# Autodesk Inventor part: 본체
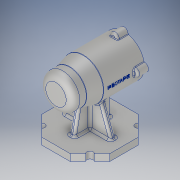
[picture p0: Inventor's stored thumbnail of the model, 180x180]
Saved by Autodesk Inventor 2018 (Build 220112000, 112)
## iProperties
Created: 2021-01
Part Number: 본체
Material: 알루미늄 6061
Document SubType Name: Modeling
Designer: home
Density: 2.7 g/cm^3
Appearance: 알루미늄 - 평지
Mass: 629.962 g
Surface Area: 613.777 cm^2
Volume: 233.319 cm^3
Author: home
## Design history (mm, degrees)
sketch "스케치1"
  geometry: L1 (0, 0)-(30, 0); L2 (30, 0)-(30, 60); L3 (30, 60)-(0, 60); L4 (0, 60)-(0, 0); L5 (30, 60)-(25, 80); L6 (25, 80)-(0, 80); L7 (0, 80)-(0, 60); L8 (0, 80)-(25, 80); L9 (25, 80)-(25, 100); L10 (25, 100)-(0, 100); L11 (0, 100)-(0, 80)
  constraints: 22 end point, 4 parallel, 3 horizontal, 3 perpendicular
  dimensions: "d5" = 30 distance of L1.start L1.end; "d6" = 60 distance of L1.end L2.end; "d9" = 20 distance of L8.end L9.end; "d10" = 25 distance of L9.end L10.end; "d11" = 100 distance between parallel lines of L1 L10
revolve "회전1" sketch "스케치1" stored, may be unused: angle "d12" = 90 deg
node "작업 평면1"
sketch "스케치2"
  geometry: L1 (0, 0)-(-21, 0); L2 (-21, 0)-(-21, 15); L3 (-21, 15)-(0, 15); L4 (0, 15)-(0, 0); L5 (0, 15)-(-24, 15); L6 (-24, 15)-(-24, 57); L7 (-24, 57)-(0, 57); L8 (0, 57)-(0, 15); L9 (0, 57)-(-21, 57); L10 (-21, 57)-(-21, 69); L11 (-21, 69)-(0, 69); L12 (0, 69)-(0, 57); L13 (0, 69)-(-17.5, 69); L14 (-17.5, 69)-(-17.5, 87); L15 (-17.5, 87)-(0, 87); L16 (0, 87)-(0, 69); L17 (0, 87)-(-16, 87); L18 (-16, 87)-(-16, 91); L19 (-16, 91)-(0, 91); L20 (0, 91)-(0, 87); L21 (0, 91)-(-10.5, 91); L22 (-10.5, 91)-(-10.5, 94); L23 (-10.5, 94)-(0, 94); L24 (0, 94)-(0, 91)
  constraints: 48 end point, 12 parallel, 6 horizontal, 6 perpendicular
  dimensions: "d14" = 15 distance of L1.end L2.end; "d15" = 21 distance of L1.start L1.end; "d16" = 42 distance of L5.end L6.end; "d17" = 24 distance of L6.end L7.end; "d18" = 12 distance of L9.end L10.end; "d19" = 21 distance of L10.end L11.end; "d20" = 18 distance of L13.end L14.end; "d21" = 17.5 distance of L14.end L15.end; "d22" = 4 distance of L17.end L18.end; "d23" = 16 distance of L18.end L19.end; "d24" = 3 distance of L21.end L22.end; "d25" = 10.5 distance of L22.end L23.end
revolve "회전2" sketch "스케치2" stored, may be unused: angle "d26" = 90 deg
chamfer "모따기1" distance "d27" = 1; stored, may be unused: second distance "d28" = 2, angle "d29" = 45 deg
fillet "모깎기1" dims "d30" = 3
fillet "모깎기2" dims "d31" = 0.3
sketch "스케치3"
  geometry: C1 r 6 at (0, -30); C2 r 6 at (30, 0); C3 r 6 at (0, 30); C4 r 6 at (-30, 0); 2 further points
  constraints: 4 centre point, 1 vertical alignment, 10 other
  dimensions: "d32" = 12 diameter of C1; "d35" = 360 deg dimension on point (0, 0) C1.centre (derived)
extrude "돌출1" join sketch "스케치3" distance "d37" = 16; taper "d38" = 0 deg
sketch "스케치4" dims "d39" = 60
  geometry: C1 r 7.5 at (0, 30) reference; 6 further points
  constraints: 1 coincident, 1 vertical alignment, 7 other
  dimensions: "d42" = 360 deg dimension on point (0, 30) point (0, 0) (derived)
hole "구멍1" sketch "스케치4" at (0, 0), (30, 30), (0, 60), (-30, 30) diameter "d44" = 3.242; stored, may be unused: countersink angle "d48" = 90 deg, drill point angle "d50" = 118 deg; dims "d45" = 8, "d46" = 4, "d47" = 2, "d49" = 10
node "작업 평면2"
sketch "스케치7"
  geometry: L1 (-20.709, 0)-(-49.998, 29.289); L2 (-49.998, 29.289)-(-49.998, 70.711); L3 (-49.998, 70.711)-(-20.709, 100); L4 (-20.709, 100)-(20.712, 100); L5 (20.712, 100)-(50.002, 70.711); L6 (50.002, 70.711)-(50.002, 29.289); L7 (50.002, 29.289)-(20.712, 0); L8 (20.712, 0)-(-20.709, 0); L9 (0, 0)-(-28.183, 0); L10 (0, 0)-(26.712, 0); 1 further point
  constraints: 20 end point, 2 horizontal, 1 collinear, 17 other
  dimensions: "d62" = 100 distance between parallel lines of L6 L2
extrude "돌출2" join sketch "스케치7" distance "d64" = 10; taper "d65" = 0 deg
sketch "스케치8"
  geometry: L1 (49.998, 70.711)-(20.709, 100) reference; L2 (20.709, 0)-(49.998, 29.289) reference; L3 (-50.002, 29.289)-(-20.712, 0) reference; L4 (-20.712, 100)-(-50.002, 70.711) reference; C1 r 4.5 at (35.354, 85.355); C2 r 4.5 at (35.354, 14.645); C3 r 4.5 at (-35.357, 14.645); C4 r 4.5 at (-35.357, 85.355); 1 further point
  constraints: 4 centre point, 4 midpoint
  dimensions: "d66" = 9 diameter of C1; "d67" = 9 diameter of C2; "d68" = 9 diameter of C3; "d69" = 9 diameter of C4
extrude "돌출3" cut sketch "스케치8" extent not by distance; stored distance "d70" = 10; taper "d71" = 0 deg
node "작업 평면3"
fillet "모깎기3" dims "d93" = 3
sketch "스케치12"
  geometry: L1 (3.998, 77)-(-4.002, 77); L2 (-4.002, 77)-(-4.002, 23); L3 (-4.002, 23)-(3.998, 23); L4 (3.998, 23)-(3.998, 77); L5 (-50.002, 70.711)-(-50.002, 29.289) reference; L6 (-20.712, 0)-(20.709, 0) reference; L7 (20.709, 100)-(-20.712, 100) reference; L8 (3.998, 50)-(-4.002, 50); 1 further point
  constraints: 10 end point, 2 midpoint, 2 parallel, 1 horizontal, 1 perpendicular
  dimensions: "d94" = 8 distance of L2.end L3.end; "d95" = 46 distance between parallel lines of L5 L2; "d97" = 23 distance between parallel lines of L6 L3; "d98" = 23 distance between parallel lines of L7 L1
extrude "돌출5" join sketch "스케치12" stored distance "d99" = 10; taper "d100" = 0 deg
node "작업 평면4"
sketch "스케치13"
  geometry: L1 (65, 100)-(65, 88.537) reference; L2 (75, 100)-(65, 100) reference; L3 (65, 77)-(23.85, 69.001); 1 further point
  constraints: 2 end point
  dimensions: "d104" = 101 deg angle of L3 L1
feature "리브3" sketch "스케치13" dims "d106" = 27, "d107" = 8, "d108" = 0, "d109" = 0, "d110" = 1, "d111" = 1
node "작업 평면5"
sketch "스케치14"
  geometry: L1 (-20.712, 65)-(-32.175, 65) reference; L2 (-35.002, 65)-(-18.69, 20.184); L3 (-50.002, 65)-(-38.539, 65) reference; L4 (-50.002, 75)-(-50.002, 65) reference; L5 (38.536, 65)-(49.998, 65) reference; L6 (49.998, 75)-(49.998, 65) reference; L7 (20.709, 65)-(32.172, 65) reference; 1 further point
  constraints: 2 end point, 1 point on line
  dimensions: "d113" = 110 deg angle of L2 L3
feature "리브4" sketch "스케치14" dims "d119" = 30, "d120" = 8, "d121" = 0, "d122" = 0, "d123" = 1, "d124" = 1
sketch "스케치15"
  geometry: L1 (38.536, 65)-(30.854, 65) reference; L2 (34.998, 65)-(18.479, 19.614); L3 (34.998, 65)-(34.998, 56.091); L4 (49.998, 75)-(49.998, 65) reference; L5 (38.536, 65)-(49.998, 65) reference; 2 further points
  constraints: 4 end point, 1 point on line, 1 vertical
  dimensions: "d125" = 15 distance between parallel lines of L4 L3; "d126" = 110 deg angle of L5 L2
feature "리브5" sketch "스케치15" dims "d127" = 30, "d128" = 8, "d129" = 0, "d130" = 0, "d131" = 1, "d132" = 1
fillet "모깎기4" dims "d133" = 3
fillet "모깎기5" dims "d134" = 3
fillet "모깎기6" dims "d135" = 3
fillet "모깎기7" dims "d136" = 1
fillet "모깎기8" dims "d137" = 10
fillet "모깎기9" dims "d138" = 3
node "작업 평면6"
sketch "스케치16"
  geometry: L1 (-29.226, 0)-(-6.771, 0) reference; 2 further points
  constraints: 1 other
  dimensions: "d140" = 38 distance from line of L1 point (0, 38); "d141" = 0 horizontal distance of point (0, 0) point (0, 38)
feature "엠보싱1" sketch "스케치16" dims "d5" = 30, "d6" = 60, "d9" = 20, "d10" = 25, "d11" = 100, "d142" = 0.5, "d143" = 0
node "솔리드1"
other parameters: "d13" = 0, "d51" = 75, "d101" = 0, "d139" = -58.75
